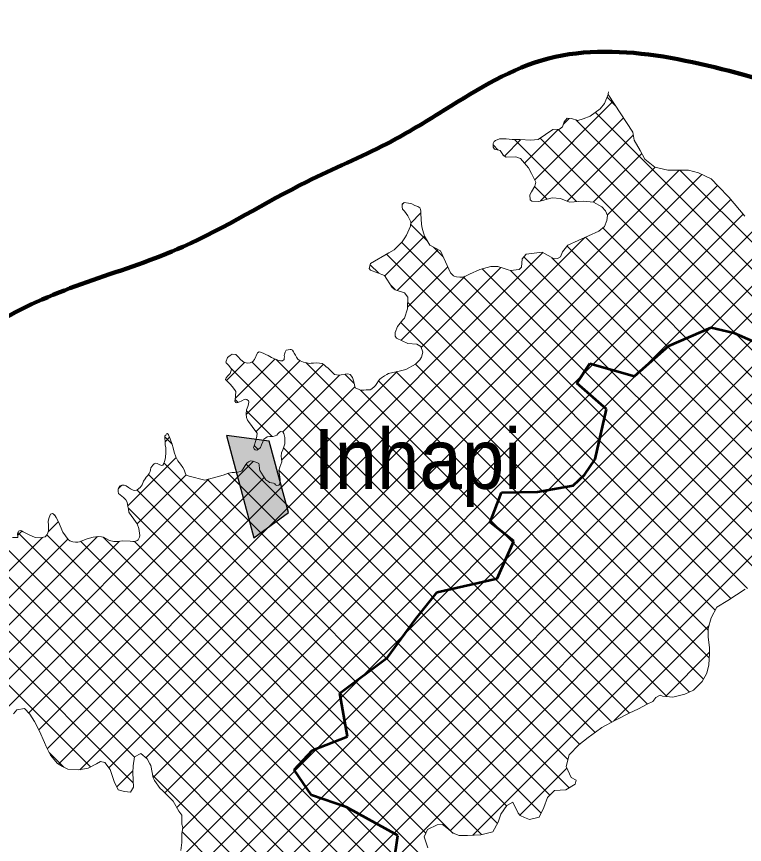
# Model space of a CAD drawing. Extents: x -1643653 to 4543381, y 1624270 to 13878484.
# Drawn here: x 635076 to 641139, y 8977144 to 8984035 of the extents above; entities that cross this region are included whole.
import ezdxf

# ---------------------------------------------------------------- set-up
doc = ezdxf.new("R2010")
doc.units = 0
doc.header["$LTSCALE"] = 200
doc.linetypes.add('MEDIUM_DASHED', pattern=[4.5, 3, -1.5])
for name, color, linetype, lineweight in [('1', 7, 'Continuous', 13), ('21', 7, 'Continuous', 25), ('26', 7, 'Continuous', 106), ('27', 7, 'Continuous', 53), ('28', 7, 'Continuous', 53), ('29', 7, 'Continuous', 13)]:
    doc.layers.add(name, color=color, linetype=linetype, lineweight=lineweight)
doc.layers.add('41', color=7, linetype='Continuous')

msp = doc.modelspace()

# ---------------------------------------------------------------- hatches: boundary and pattern name
at = {"layer": '21'}
msp.add_hatch(color=256, dxfattribs=at).paths.add_polyline_path([(636825.6, 8980547.8), (637053.8, 8979697.3), (637340.6, 8979906.6), (637180.8, 8980499.4)])

# ---------------------------------------------------------------- linework, layer by layer
at = {"layer": '1', "lineweight": 25}
msp.add_spline([(814781, 9009175.5), (814787.2, 9009173.4), (814796.9, 9009173.4), (814799.4, 9009172.4), (814805.1, 9009174.5), (814805.6, 9009176.5), (814811.7, 9009179.5), (814811.7, 9009179.5), (814801.5, 9009181), (814790.7, 9009181.5), (814784.1, 9009183.1), (814777.4, 9009185.1), (814778.4, 9009175.5)], degree=3, dxfattribs=at)
at = {"layer": '21'}
msp.add_lwpolyline([(636825.6, 8980547.8), (637053.8, 8979697.3), (637340.6, 8979906.6), (637180.8, 8980499.4)], close=True, dxfattribs=at)
at = {"layer": '26'}
msp.add_spline([(593042.9, 8976356.4), (593459.4, 8976419.7), (594161.8, 8976760.1), (594545.8, 8977114.6), (594814.3, 8977291.5), (596052.8, 8977846), (596780.5, 8978160.9), (597647.4, 8978322.7), (598691.5, 8978280.2), (599825, 8978301), (600207.2, 8978324.8), (600219.9, 8978324.8), (601225.9, 8978295.2), (602040.5, 8978228.3), (602729, 8978352.6), (603275.7, 8978615.7), (603826.1, 8978691.5), (605382.2, 8979104.7), (606925.6, 8979530.7), (607614.7, 8979782.2), (608494.2, 8979905.8), (609628.7, 8980104.6), (610966.5, 8980200.8), (612239.3, 8980081.1), (613131.4, 8980179.2), (614149.6, 8980073.3), (614581.8, 8979931.6), (616361, 8979275.7), (617566.6, 8978533.2), (618237.8, 8977881.9), (618833.2, 8977319.9), (619759.6, 8976743.8), (620623, 8976295.2), (621512.5, 8975960.9), (621945, 8975870.1), (622544.2, 8975982.1), (622735.8, 8976070.3), (623374, 8976322), (623974.5, 8976675.6), (624627.1, 8977219.8), (625050.7, 8977803), (625410.5, 8978361.1), (625972.2, 8978587.6), (626239.9, 8978637.4), (628239.2, 8978616.5), (629272.1, 8978853.8), (630051.8, 8979346.6), (630703.5, 8979738.1), (631164.1, 8980105), (631534.8, 8980357.8), (632185.7, 8980596.8), (632989, 8980758.8), (633690, 8980870.4), (634328.2, 8981109.3), (634980.1, 8981526.3), (636460.7, 8982117.9), (637495.4, 8982660.5), (638159.4, 8982975.7), (638593.8, 8983228.2), (639449.6, 8983669.8), (641371.6, 8983483.9), (642032.9, 8983315.8), (642528.8, 8983186.6), (643277.3, 8982687.6), (644168, 8982544), (644675.9, 8982274.9), (645321.7, 8981636.4), (645853, 8981011.1), (646805.1, 8980473.1), (647606.1, 8980240.8), (648482.7, 8979868.5), (649626.6, 8979469.5), (650871.6, 8978943), (651404, 8978495.7), (652521.8, 8977995.2), (653308.2, 8977445.1), (653712.6, 8976883.9), (654308.9, 8976487.2), (655070.4, 8976039), (655983.7, 8975399.4)], degree=3, dxfattribs=at)
at = {"layer": '27', "linetype": 'MEDIUM_DASHED'}
msp.add_lwpolyline([(638219.3, 8976988.1), (638253.1, 8977218.9), (637825.5, 8977453.5), (637534.3, 8977554.8), (637388.8, 8977763.8), (637540.7, 8977928.5), (637831.8, 8978042.5), (637768.5, 8978403.5), (638167.3, 8978699.2), (638401.5, 8979022.2), (638578.7, 8979243.9), (639078.8, 8979357.9), (639218, 8979668.2), (639021.8, 8979826.6), (639116.7, 8980073.6), (639414.2, 8980079.9), (639711.7, 8980130.6), (639806.7, 8980219.2), (639895.3, 8980352.2), (639990.2, 8980768.3), (639743.4, 8980983.7), (639851, 8981148.3), (640224.4, 8981040.7), (640509.2, 8981294), (640861.8, 8981446), (641051.7, 8981401.7), (641342.8, 8981275)], dxfattribs=at)
at = {"layer": '27'}
msp.add_spline([(634685, 8981342.6), (634980.1, 8981526.3), (636460.7, 8982117.9), (637495.4, 8982660.5), (638159.4, 8982975.7), (638593.8, 8983228.2), (639449.6, 8983669.8), (641371.6, 8983483.9), (642032.9, 8983315.8), (642528.8, 8983186.6), (643277.3, 8982687.6), (644168, 8982544), (644540.6, 8982372.7)], degree=3, dxfattribs=at)
at = {"layer": '28'}
msp.add_spline([(644540.6, 8982372.7), (644168, 8982544), (643277.3, 8982687.6), (642528.8, 8983186.6), (642032.9, 8983315.8), (641371.6, 8983483.9), (639449.6, 8983669.8), (638593.8, 8983228.2), (638159.4, 8982975.7), (637495.4, 8982660.5), (636460.7, 8982117.9), (634980.1, 8981526.3), (634328.2, 8981109.3), (633690, 8980870.4), (632989, 8980758.8), (632185.7, 8980596.8), (631534.8, 8980357.8), (631164.1, 8980105), (630703.5, 8979738.1), (630051.8, 8979346.6), (629272.1, 8978853.8), (628372, 8978627.3)], degree=3, dxfattribs=at)
at = {"layer": '29'}
for p, q in [((640065.3, 8983293), (639994.8, 8983363.5)), ((639392, 8982676.1), (640043, 8983327.1)), ((642744.4, 8980389.4), (639897, 8983236.8)), ((639440.9, 8982500.5), (640131.9, 8983191.5)), ((639630.5, 8983139.1), (639679, 8983187.6)), ((642693.6, 8980215.7), (639733.5, 8983175.8)), ((639306.6, 8982815.2), (639587.5, 8983096.1)), ((642889.4, 8979795.4), (639588.7, 8983096.1)), ((639140, 8982873.1), (639277.4, 8983010.6)), ((639741.4, 8982494.4), (639223.9, 8983011.9)), ((642867.7, 8979592.6), (639437.2, 8983023.1)), ((639662, 8982497.1), (640213.3, 8983048.4)), ((639088.5, 8982922.8), (639045.3, 8982966)), ((639135.6, 8982875.7), (639127.4, 8982883.9)), ((639880.1, 8982490.6), (640283.3, 8982893.8)), ((635603.7, 8977765.3), (640595.3, 8982756.8)), ((639996.8, 8982382.9), (640394.1, 8982780.1)), ((642800.9, 8980557.4), (640601.4, 8982756.9)), ((635844.9, 8977781.9), (640784, 8982721.1)), ((636153.4, 8977865.9), (640915.5, 8982628.1)), ((639495.8, 8982515.4), (639392.2, 8982619)), ((636213.9, 8977701.9), (641024.3, 8982512.4)), ((638288.8, 8982470.9), (638305.9, 8982488.1)), ((636311.2, 8977574.7), (641127.5, 8982391)), ((638359, 8982316.6), (638444.4, 8982402)), ((636411.6, 8977450.6), (641242.4, 8982281.5)), ((638499, 8982165.2), (638357.8, 8982306.4)), ((642782.3, 8979453.5), (639959.1, 8982276.7)), ((635426.6, 8977812.6), (639809.4, 8982195.5)), ((638142.4, 8981875.6), (638474.9, 8982208)), ((642632.2, 8979379.1), (639813.8, 8982197.5)), ((636458.8, 8977273.3), (641350.8, 8982165.4)), ((641165.2, 8979274.6), (638283.3, 8982156.4)), ((638630.1, 8982034.1), (638548.5, 8982115.8)), ((642494.3, 8979292.5), (639661.9, 8982124.9)), ((635330.5, 8977941.1), (639459.4, 8982070)), ((636415.8, 8977005.8), (641454.2, 8982044.3)), ((641024.9, 8979190.3), (638157.4, 8982057.9)), ((638246.9, 8981755.5), (638587, 8982095.6)), ((642062.2, 8979275.6), (639301.8, 8982035.9)), ((636427, 8976792.5), (641604.2, 8981969.7)), ((638093.1, 8981897.7), (638021.5, 8981969.2)), ((641905.1, 8979657.1), (639534.7, 8982027.6)), ((636426.7, 8976567.7), (641801.5, 8981942.5)), ((636512.5, 8976429), (642006.8, 8981923.3)), ((636623, 8976315), (642213.8, 8981905.8)), ((636742.9, 8976210.4), (642445.1, 8981912.6)), ((638332.5, 8981616.6), (638667.9, 8981952)), ((638445.8, 8981280.9), (639110.9, 8981946)), ((642531.2, 8978357.5), (638953.2, 8981935.5)), ((642086.3, 8979026.9), (639191, 8981922.2)), ((636884.6, 8976127.6), (642621.8, 8981864.8)), ((638280.4, 8981340), (638813.4, 8981873)), ((642449.7, 8978214.6), (638797, 8981867.3)), ((638228.9, 8981761.8), (638192.6, 8981798.2)), ((638875.8, 8977220.7), (643461.1, 8981806.1)), ((636966.4, 8975984.9), (642723.1, 8981741.6)), ((638688.3, 8977257.8), (643140.4, 8981709.9)), ((637013.2, 8975807.2), (642867.7, 8981661.7)), ((640896.1, 8979094.7), (638333.2, 8981657.5)), ((640837.6, 8978928.6), (638277.2, 8981489)), ((636824.3, 8981006.5), (636974, 8981156.1)), ((636898, 8980855.6), (637226.9, 8981184.5)), ((636989.4, 8980722.5), (637437, 8981170.1)), ((640033, 8978161.7), (637035, 8981159.7)), ((637071.8, 8980580.4), (637631.7, 8981140.3)), ((640181.8, 8978237.3), (637238.8, 8981180.4)), ((640331.2, 8978312.4), (637489.9, 8981153.7)), ((640845.6, 8978696.1), (638399.8, 8981142)), ((635262.3, 8978097.4), (638245.3, 8981080.4)), ((639894.6, 8978075.6), (636855, 8981115.1)), ((640797, 8978520.2), (638238.4, 8981078.8)), ((637294.3, 8980578.4), (637766, 8981050.1)), ((637888.3, 8980979.9), (637810.8, 8981057.4)), ((640680.2, 8978412.4), (638090.9, 8981001.8)), ((637284.1, 8980343.7), (637894.7, 8980954.2)), ((640493, 8978375.2), (637941.9, 8980926.3)), ((636922.6, 8980823), (636897.3, 8980848.4)), ((637205.5, 8980540.2), (636991.7, 8980754)), ((636371.9, 8980475.7), (636311.3, 8980536.3)), ((636313.5, 8980495.6), (636350.9, 8980533.1)), ((637089.1, 8980432.1), (637056.3, 8980464.9)), ((639766.2, 8977979.5), (637299.3, 8980446.4)), ((634619.7, 8977903.8), (637049, 8980333.1)), ((636003.8, 8979961.5), (636406.3, 8980364)), ((639157.7, 8977465.4), (636305, 8980318.1)), ((639680.2, 8977616.4), (636988, 8980308.7)), ((639668.9, 8977852.3), (637261.6, 8980259.5)), ((634505.3, 8978013.9), (636675.3, 8980183.9)), ((635178.6, 8978238.2), (637139.5, 8980199.1)), ((636079.7, 8979812.8), (636488.7, 8980221.8)), ((639081.2, 8977317.4), (636176.1, 8980222.6)), ((639444.5, 8977403.1), (636666.3, 8980181.4)), ((639517.9, 8977554.3), (636839.7, 8980232.4)), ((635925.5, 8980107.6), (635951, 8980133.1)), ((638948.3, 8977225.8), (636080, 8980094.1)), ((638373.5, 8976004.6), (634471, 8979907.1)), ((639044.7, 8975557.8), (634688.8, 8979913.7)), ((638710.4, 8977239.2), (636007.5, 8979942.1)), ((638140.1, 8976013.4), (634306, 8979847.6)), ((635339.1, 8979745.7), (635425.2, 8979831.9)), ((635399.7, 8979876.4), (635381.4, 8979894.7)), ((633889, 8978295.6), (635293.5, 8979700.1)), ((634120.5, 8978078.2), (635749.7, 8979707.3)), ((636057.6, 8977871.5), (634177, 8979752)), ((635085.1, 8979716.3), (635121.1, 8979752.3)), ((638671.3, 8976155.8), (635087, 8979740.1)), ((638468, 8976583.6), (635329.9, 8979721.6)), ((638702.6, 8976798), (635798.4, 8979702.2)), ((635691.2, 8977788.9), (633826.6, 8979653.4)), ((636048, 8977656.5), (634029.2, 8979675.3)), ((634042.7, 8978224.9), (635504, 8979686.1)), ((634221.6, 8977954.7), (635934.9, 8979668)), ((638679.4, 8976596.6), (635608.5, 8979667.6)), ((638486.5, 8977238.6), (636060, 8979665.1)), ((640051.5, 8978172), (640843.5, 8978963.9)), ((640480.5, 8978376.4), (640847.6, 8978743.6)), ((635469, 8977786.6), (635347.2, 8977908.4)), ((639268, 8977388.4), (639659.5, 8977780)), ((635910.5, 8977623.1), (636045, 8977757.6)), ((637863.9, 8976065.1), (636210.9, 8977718.1)), ((637665, 8976039.5), (636455.1, 8977249.5))]:
    msp.add_line(p, q, dxfattribs=at)
for points in [[(639999.1, 8982377.9), (639981.1, 8982417), (639950.5, 8982452.3), (639882.4, 8982490.4), (639796.3, 8982499.5), (639682.5, 8982488.9), (639605.6, 8982519.7), (639536.1, 8982526.4), (639425.2, 8982496.2), (639368.9, 8982498), (639354.5, 8982509.1), (639350.1, 8982550.2), (639366.1, 8982575.1), (639394, 8982622), (639401.7, 8982656.9), (639365.1, 8982728.9), (639340.4, 8982777.1), (639272.8, 8982853.3), (639233.4, 8982866.9), (639153.3, 8982865.5), (639131.4, 8982878.1), (639103.1, 8982919), (639057.9, 8982930.7), (639045.3, 8982948.6), (639045.4, 8982979.3), (639054.4, 8982994.5), (639064.2, 8983002.1), (639099.9, 8983017.8), (639155.3, 8983016.6), (639204.4, 8983012.3), (639269, 8983011), (639358.6, 8983006.5), (639422, 8983012.6), (639542.8, 8983095.4), (639597.1, 8983096.3), (639623.5, 8983117.2), (639637, 8983159.5), (639661.2, 8983188.7), (639697.8, 8983186.4), (639751.8, 8983170.4), (639795.9, 8983184.9), (639853.5, 8983205.7), (639895.6, 8983235.8), (639936.5, 8983267.3), (639973.7, 8983311.1), (640004.1, 8983386.4)], [(640004.1, 8983386.4), (640004.4, 8983393), (640005.2, 8983408.2)], [(640004.1, 8983386.4), (640209.2, 8983073.5), (640220.2, 8983007.2), (640269.1, 8982919.1), (640309.3, 8982847.5), (640391.5, 8982780.7), (640499.4, 8982755.7), (640631.7, 8982757.3), (640673.7, 8982755.7), (640756.2, 8982734.7), (640861.4, 8982683), (640923.3, 8982620.2), (641007.9, 8982531.7), (641142.8, 8982373)], [(637908.3, 8980939.4), (637925, 8980932.6), (637934.8, 8980928.6), (637948.5, 8980924.2), (637967.9, 8980925.5), (637987.9, 8980926.9), (638006.2, 8980928.1), (638022.5, 8980929.3), (638035, 8980937.4), (638056.8, 8980955), (638065.4, 8980963.4), (638076.5, 8980980.1), (638092.3, 8981003.9), (638100.7, 8981016.6), (638116, 8981026.9), (638141.9, 8981044), (638161.5, 8981057), (638175.2, 8981063.9), (638210.3, 8981072.1), (638262.5, 8981084.5), (638318, 8981098.3), (638399, 8981141.2), (638434.5, 8981177.4), (638449.3, 8981199.3), (638460.2, 8981242.4), (638442.9, 8981288.8), (638409.4, 8981309.2), (638334.2, 8981313.6), (638242.1, 8981358.8), (638229.2, 8981375.1), (638230, 8981405.6), (638249.9, 8981455.9), (638294.8, 8981510.3), (638307.4, 8981525.6), (638332.2, 8981602.5), (638334, 8981699.1), (638307, 8981735), (638229.4, 8981761.4), (638204.1, 8981780.4), (638139.7, 8981879.8), (638024.7, 8981923.9), (638014.3, 8981936.6), (638023.6, 8981978.4), (638176.5, 8982069.2), (638221.3, 8982092.2), (638253.7, 8982126.2), (638272.3, 8982144.1), (638287.4, 8982161), (638309, 8982191.9), (638325.1, 8982214.8), (638356.1, 8982291.4), (638360.1, 8982326.5), (638335.5, 8982376.7), (638306.2, 8982414.3), (638291.9, 8982432.6), (638288.8, 8982449.8), (638288.8, 8982472.9), (638305.2, 8982488.2), (638341.4, 8982481.3), (638368.2, 8982475.2), (638394, 8982463.6), (638417.7, 8982453), (638436.2, 8982444), (638440.3, 8982431), (638443.8, 8982412.3), (638444.9, 8982393.9), (638447.2, 8982351.6), (638449.8, 8982305.4), (638454.9, 8982274.8), (638460.8, 8982254.9), (638475.3, 8982206.7), (638518.3, 8982131.6), (638606.6, 8982085.3), (638691.1, 8981901.7), (638715.2, 8981875.6), (638721.6, 8981873.9), (638741.9, 8981868.4), (638767.1, 8981865.8), (638794.2, 8981866.4), (638810.9, 8981871.8), (638848.2, 8981889.6), (638933.7, 8981930.5), (639025.4, 8981954), (639084.1, 8981954.3), (639128.1, 8981940.7), (639172.3, 8981927), (639190.6, 8981922.2), (639262, 8981928.2), (639281.5, 8981949.9), (639286.9, 8982018.7), (639321.4, 8982058.5), (639454.7, 8982072.6), (639553.4, 8982017), (639582.1, 8982020.2), (639607.3, 8982034.2), (639623.9, 8982076.3), (639666.6, 8982130.9), (639924.8, 8982247.7), (639973.1, 8982288.5), (639993.8, 8982336.8), (639999.1, 8982377.9)], [(637263.9, 8980574.1), (637253.5, 8980562.2), (637244, 8980551.9), (637231, 8980544.4), (637211.6, 8980540.1), (637187.1, 8980540.4), (637164.9, 8980537.5), (637152.1, 8980528.4), (637137, 8980516.5), (637127.6, 8980495.8), (637116.5, 8980470.1), (637108.4, 8980446.8), (637092.4, 8980433.5), (637076.3, 8980426.7), (637063.4, 8980429.4), (637055.6, 8980437.9), (637051.2, 8980447.5), (637055.3, 8980462.1), (637070.1, 8980505.4), (637079, 8980542.3), (637079.7, 8980566.9), (637070.7, 8980582.5), (637007.4, 8980664.4), (636998.9, 8980674.7), (636992.9, 8980697.4), (636988.6, 8980728), (636992.5, 8980761), (637001.4, 8980790.3), (637007.5, 8980809.9), (637012.1, 8980827.3), (637009.5, 8980837.6), (636994.1, 8980846.7), (636981.1, 8980850.3), (636973.1, 8980846.8), (636951.9, 8980837.2), (636928.2, 8980825), (636910.8, 8980818.9), (636901.9, 8980823.4), (636895.1, 8980833.1), (636897.5, 8980849.5), (636899.1, 8980868.6), (636900.6, 8980886.9), (636902.3, 8980906.2), (636902.1, 8980915.5), (636892.2, 8980930.4), (636873.4, 8980956.5), (636855.3, 8980974.9), (636827.1, 8981003.6), (636816.6, 8981014.3), (636821, 8981027.6), (636834.9, 8981043.7), (636847.8, 8981055.5), (636855.5, 8981064.7), (636865.6, 8981098), (636854.3, 8981116.3), (636837.6, 8981135.6), (636821.2, 8981153.8), (636818.5, 8981158.9), (636832.8, 8981196.5), (636856.1, 8981214.7), (636873, 8981225.2), (636902.6, 8981220.8), (636918.4, 8981205.6), (636944.8, 8981179), (636970.5, 8981157.1), (636998.1, 8981149.3), (637022.8, 8981153.2), (637043, 8981163.9), (637058.2, 8981180.9), (637084.1, 8981235.8), (637095.9, 8981243.2), (637109.2, 8981241.1), (637129.6, 8981233.1), (637152.2, 8981222.4), (637171.7, 8981213.2), (637200.2, 8981196.6), (637218.3, 8981187.5), (637252.3, 8981175.7), (637273.4, 8981169.7), (637290.8, 8981169.9), (637304.3, 8981181.1), (637306.3, 8981191.5), (637308.4, 8981202.6), (637304.9, 8981215), (637307.1, 8981226.1), (637314.4, 8981241.3), (637323, 8981256.9), (637339.8, 8981260.1), (637355.2, 8981263), (637364.3, 8981263.6), (637373.6, 8981257.8), (637382.1, 8981244.7), (637389.4, 8981232), (637398.6, 8981215.9), (637408.1, 8981199.3), (637420.4, 8981184.6), (637439.5, 8981168), (637465.2, 8981157.3), (637485.5, 8981154.7), (637513.3, 8981148.4), (637529.6, 8981149.2)], [(637529.6, 8981149.2), (637550.9, 8981150.3), (637576.8, 8981151.6), (637600.3, 8981150.7), (637620.5, 8981146.8), (637638.9, 8981136.3), (637653.1, 8981122.6), (637671.3, 8981109.3), (637725.5, 8981055.8), (637761.8, 8981049.4), (637835.1, 8981061.3), (637855.2, 8981054.6), (637873.8, 8981031.4), (637884.4, 8980995.8), (637897.2, 8980943.9), (637908.3, 8980939.4)], [(635923, 8980100.3), (635928.2, 8980115.9), (635940.7, 8980128.3), (635951.9, 8980133.6), (635971.5, 8980135.2), (635989.2, 8980128.2), (636008.1, 8980116), (636024.8, 8980104.8), (636046.8, 8980094.1), (636060.9, 8980089.3), (636077.1, 8980091.9), (636095.9, 8980106), (636106.3, 8980115.6), (636123.4, 8980137.3), (636134.3, 8980166.4), (636146.8, 8980187.4), (636156.4, 8980200.3), (636170.8, 8980214.8), (636182, 8980231.3), (636189.5, 8980247.8), (636191.3, 8980262.1), (636194.2, 8980279.3), (636210.5, 8980300.2), (636222.2, 8980312.8), (636233.4, 8980316.7), (636246.6, 8980313.6), (636264.6, 8980305.8), (636283.3, 8980298.9), (636295.5, 8980301.7), (636303.5, 8980313.8), (636309.9, 8980332), (636316.6, 8980362.5), (636320.5, 8980408.9), (636321.1, 8980445.4), (636315.3, 8980470.7), (636313, 8980501.7), (636310.8, 8980522.3), (636311.7, 8980545.5), (636318.6, 8980551.8), (636326.6, 8980563.1), (636332.9, 8980564), (636341.3, 8980554.6), (636348.6, 8980539.1), (636355.9, 8980520.1), (636372.6, 8980473.7), (636379.8, 8980445.6), (636389.9, 8980409.5), (636403.6, 8980369.1), (636420.2, 8980337.8), (636440.7, 8980310.1), (636461.7, 8980281.8), (636471.3, 8980260.9), (636482.1, 8980236.5), (636489.9, 8980219), (636513, 8980210.7), (636645.9, 8980175.7), (636796.3, 8980217.7), (636842.9, 8980233.5), (636870.9, 8980239.2), (636891.2, 8980241.1), (636918, 8980243.1), (636940.3, 8980247.1), (636951.4, 8980254.7), (636964.1, 8980271.7), (636981.1, 8980298), (636993.8, 8980317.7), (637007.4, 8980329), (637024.2, 8980337.2), (637040.8, 8980335.2), (637061.9, 8980329.8), (637084.1, 8980320.3), (637094.5, 8980314.1), (637096.7, 8980304.8), (637100.8, 8980271.2), (637101.6, 8980256.8), (637130.8, 8980211.7), (637153.9, 8980178.2), (637178.4, 8980162.1), (637182.5, 8980157.4), (637215.3, 8980152.1), (637226.7, 8980144.3), (637233.5, 8980138.2), (637245, 8980133.1), (637260.5, 8980134.5), (637267.5, 8980140.7), (637271.2, 8980158.6), (637270.6, 8980180.4), (637260.7, 8980256.7), (637270.2, 8980284.5), (637286.8, 8980327.9), (637282.6, 8980352.4), (637279.4, 8980376), (637284.4, 8980404.3), (637293.5, 8980428.8), (637309.6, 8980477.8), (637310.4, 8980499.3), (637311, 8980531.1), (637302.1, 8980565.8), (637294, 8980578.7), (637275.6, 8980581.1), (637263.9, 8980574.1)], [(635041.5, 8979699.3), (635088.2, 8979698.4), (635086.7, 8979706), (635083.3, 8979729.1), (635089, 8979746.3), (635093.2, 8979751.7), (635110.3, 8979755.8), (635117.4, 8979754.4), (635131.8, 8979745.9), (635174.9, 8979722.6), (635230.9, 8979699.3), (635273, 8979695.7), (635316, 8979705), (635332.3, 8979724.5), (635341.3, 8979752.7), (635341.9, 8979798.1), (635340, 8979835.8), (635347.3, 8979864.2), (635359.3, 8979892.3), (635377.1, 8979897.4), (635392.4, 8979887.7), (635406.5, 8979865.7), (635427.1, 8979828.5), (635461.6, 8979743.7), (635506.7, 8979682.3), (635520.2, 8979670.6), (635543.8, 8979662.9), (635568.3, 8979659.1), (635586.1, 8979659.7), (635599.4, 8979664.1), (635664.9, 8979689.1), (635714.5, 8979702.8), (635759.8, 8979708.6), (635784.5, 8979705.2), (635800.3, 8979701.8), (635826.8, 8979688), (635851.2, 8979674.3), (635886.3, 8979666.4), (635920, 8979666.6), (635961.2, 8979670.5), (636021.6, 8979668.7), (636044.5, 8979666.5), (636062.9, 8979664.9), (636081.5, 8979673.3), (636090.3, 8979679.1), (636101.6, 8979700.4), (636103.8, 8979715.4), (636100.2, 8979734.5), (636095, 8979772.5), (636080, 8979812.2), (636054.5, 8979852.4), (636031.5, 8979881.8), (636016.3, 8979900.3), (636012.6, 8979910.3), (636009.1, 8979934.1), (636004.5, 8979958.2), (635998, 8979992), (635985.9, 8980012.7), (635967.1, 8980032.1), (635924.9, 8980065.6), (635922, 8980080.4), (635923, 8980100.3)], [(638502.1, 8977115), (638472.3, 8977206.8), (638499.5, 8977267.7), (638578.7, 8977306.5), (638624.5, 8977311.3), (638659.9, 8977281.7), (638711.7, 8977238.1), (638762.5, 8977218.6), (638831.2, 8977218.1), (638944.5, 8977224.8), (639043.9, 8977249.5), (639087.7, 8977329.3), (639108.6, 8977395.3), (639160.1, 8977468.7), (639209.9, 8977495.1), (639255, 8977405.7), (639271.4, 8977383.9), (639306.9, 8977368.4), (639347.5, 8977351.5), (639429, 8977371.3), (639467.8, 8977451.1), (639497.7, 8977534.9), (639558, 8977592.9), (639652.2, 8977599.9), (639728.8, 8977645.1), (639736.7, 8977679.4), (639694.9, 8977700), (639653.6, 8977793.2), (639678.5, 8977889.7), (639758.1, 8977973.1), (639836.1, 8978034.8), (639897.5, 8978077.6), (639951.3, 8978116.7), (640065, 8978179.4), (640178.6, 8978235.8), (640256.5, 8978273.3), (640328.1, 8978311), (640376.6, 8978333.5), (640399.7, 8978367.7), (640436.8, 8978387.7), (640457.1, 8978378.7), (640542.3, 8978370.4), (640642.9, 8978393.8), (640713.2, 8978428.9), (640786.3, 8978500.9), (640825, 8978570.5), (640842, 8978637.8), (640847.8, 8978733.2), (640846.9, 8978781.6), (640836.2, 8978873.3), (640838, 8978941.9), (640860.3, 8979030.8), (640909.3, 8979118.2), (641001.3, 8979174.8), (641144.5, 8979269.1)], [(636187.2, 8977815.4), (636163.4, 8977857.5), (636112.8, 8977899.9), (636057.9, 8977873.6), (636047.1, 8977797.3), (636044.1, 8977741.4), (636049.6, 8977621.8), (636025.1, 8977578.7), (635975.5, 8977584.2), (635923.5, 8977597.3), (635888.4, 8977667.5), (635854.8, 8977768.3), (635812, 8977827.1), (635776.4, 8977835), (635743.2, 8977816.2), (635671.7, 8977778.6), (635596.5, 8977763.9), (635502.4, 8977771), (635458, 8977791.7), (635417.5, 8977818.7), (635358.2, 8977886.6), (635321.9, 8977958.1), (635308.2, 8977993.8), (635266.9, 8978088.3), (635226.8, 8978167.5), (635187.8, 8978228.8), (635142.4, 8978275), (635077.4, 8978264), (635051.7, 8978229.9)], [(636443.8, 8977094.6), (636451.9, 8977160.7), (636452.5, 8977233.2), (636460.5, 8977284), (636453.1, 8977312.1), (636452.4, 8977388.4), (636428.5, 8977421.7), (636380.7, 8977503.5), (636331.5, 8977553.5), (636289.9, 8977597), (636273.4, 8977608.6), (636225.6, 8977677.7), (636214.3, 8977699.4), (636196, 8977801.3), (636187.2, 8977815.4)]]:
    msp.add_lwpolyline(points, dxfattribs=at)
at = {"layer": '29', "lineweight": 53}
msp.add_spline([(644540.6, 8982372.7), (644168, 8982544), (643277.3, 8982687.6), (642528.8, 8983186.6), (642032.9, 8983315.8), (641371.6, 8983483.9), (639449.6, 8983669.8), (638593.8, 8983228.2), (638159.4, 8982975.7), (637495.4, 8982660.5), (636460.7, 8982117.9), (634980.1, 8981526.3), (634328.2, 8981109.3), (633690, 8980870.4), (632989, 8980758.8), (632185.7, 8980596.8), (631534.8, 8980357.8), (631164.1, 8980105), (630703.5, 8979738.1), (630051.8, 8979346.6), (629272.1, 8978853.8), (628372, 8978627.3)], degree=3, dxfattribs=at)

# ---------------------------------------------------------------- texts
at = {"layer": '41', "width": 0.95}
msp.add_text('Inhapi', height=500, dxfattribs=at).set_placement((637549, 8980103.2))

doc.saveas('drawing.dxf')
